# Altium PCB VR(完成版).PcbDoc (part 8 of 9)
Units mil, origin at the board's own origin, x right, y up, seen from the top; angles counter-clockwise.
Board outline 2839.68 x 2020.7 mil, 6 copper layers (TOP, GND02, SIN03, SIN04, PWR05, BOTTOM); 494 components, 404 nets, 7124 pads, 1123 vias.
Unrouted connection lines stored in the file: 10.
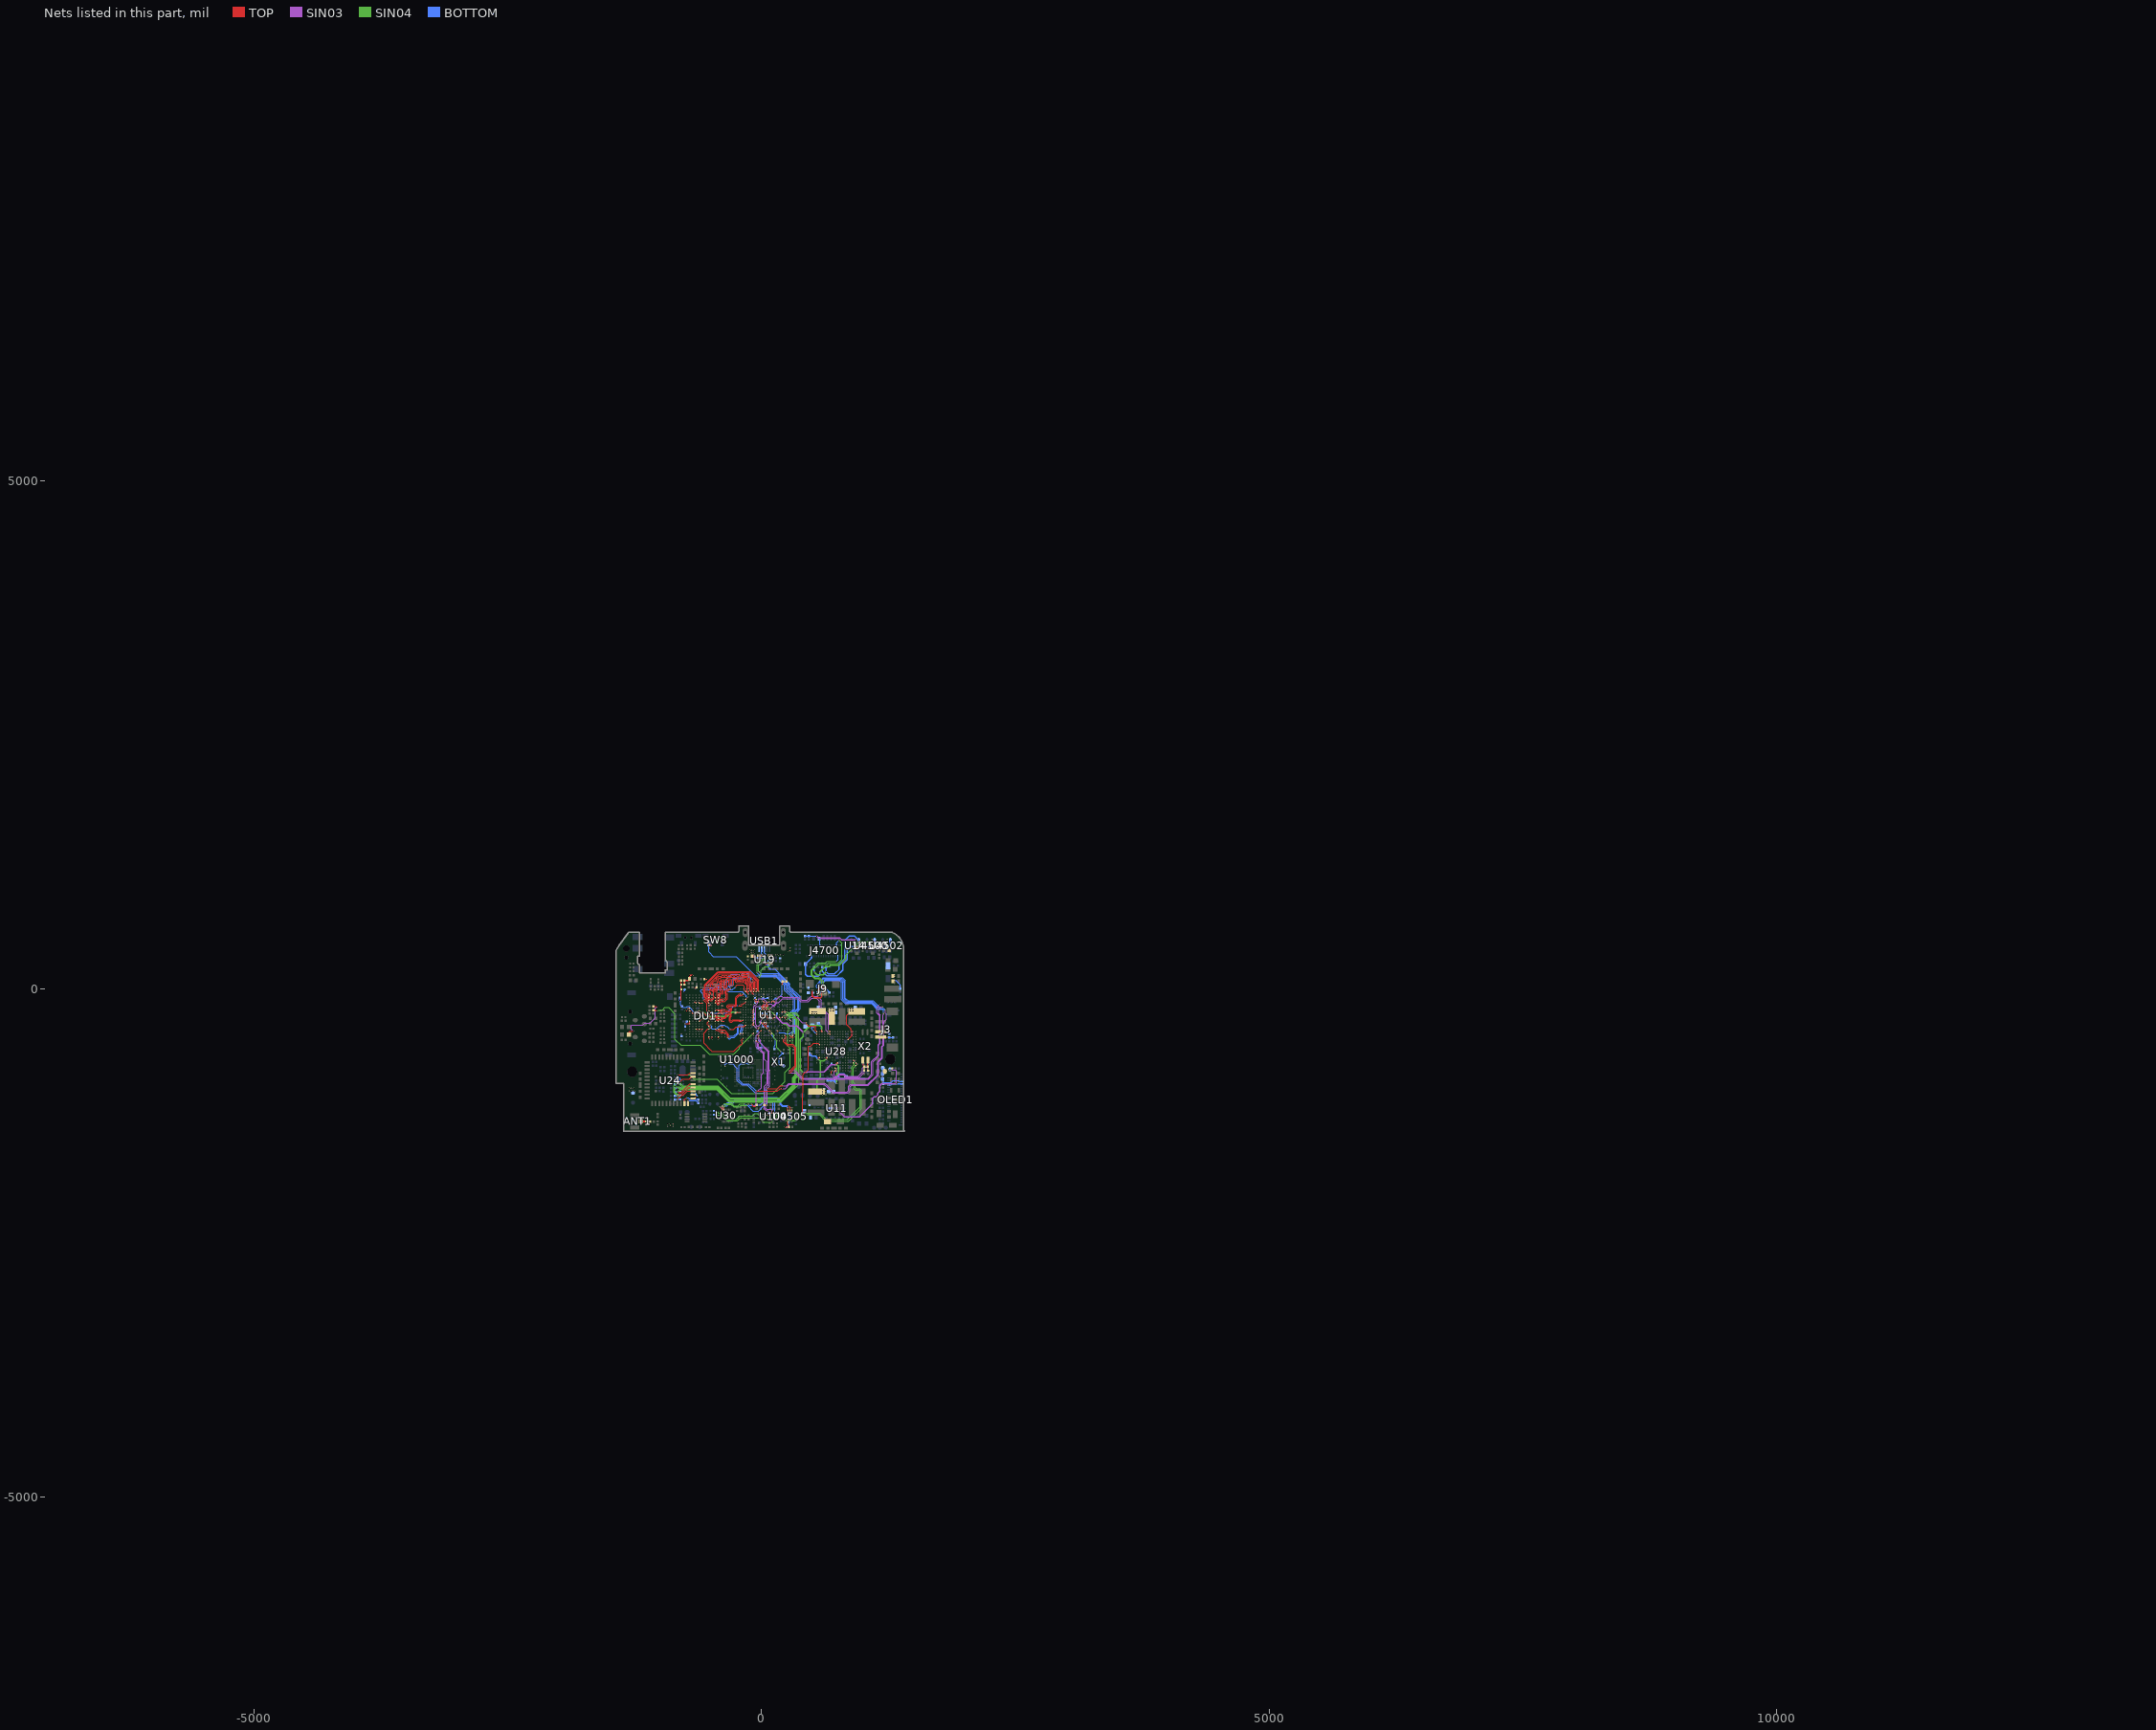
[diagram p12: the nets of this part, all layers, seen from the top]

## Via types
v1: diameter 14, hole 8, TOP to BOTTOM, tented both sides, 707 vias
v2: diameter 16, hole 10, TOP to BOTTOM, tented both sides, 275 vias
v3: diameter 16, hole 8, TOP to BOTTOM, tented both sides, 134 vias
v4: diameter 8, hole 8, TOP to BOTTOM, tented both sides, 3 vias
v5: diameter 10, hole 10, TOP to BOTTOM, tented both sides, 2 vias
v6: diameter 14, hole 8, TOP to BOTTOM, tented top, 1 vias
v7: diameter 14, hole 10, TOP to BOTTOM, tented both sides, 1 vias

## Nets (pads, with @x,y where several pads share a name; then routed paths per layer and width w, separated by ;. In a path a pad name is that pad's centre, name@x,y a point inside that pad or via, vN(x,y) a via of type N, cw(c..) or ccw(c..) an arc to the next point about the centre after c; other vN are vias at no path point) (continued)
SDQ24: DU1.B11 U1.A4 | length 880.9
  TOP w3.8: -415.58,-73.58 -411.3,-69.3 -411.3,-49.3
  TOP w4: DU1.B11@-423.02,-87.89 -415.58,-80.45 -415.58,-73.58 ; -411.3,-49.3 -401.81,-39.81 -393.01,-39.81 -389.01,-35.81 -389.01,-27.81 -393.01,-23.81 -404.01,-23.81 -406.01,-21.81 -406.01,-10.05 -410.01,-6.05 -415.01,-6.05 -419.01,-2.05 -419.01,5.95 -415.01,9.95 -410.01,9.95 -406.01,13.95 -406.01,21.95 -410.01,25.95 -415.01,25.95 -419.01,29.95 -419.01,37.95 -415.01,41.95 -410.01,41.95 -406.01,45.95 -406.01,53.95 -410.01,57.95 -415.01,57.95 -419.01,61.95 -419.01,69.95 -415.01,73.95 -410.01,73.95 -390.98,92.98 -369.01,92.98 -364.01,87.98 -364.01,21.98 -360.01,17.98 -355.01,17.98 -351.01,21.98 -351.01,92.95 -342.98,100.98 -309.01,100.98 -304.01,95.98 -304.01,52.98 -299.01,47.98 -293.01,47.98 -289.01,51.98 -289.01,87.98 -276.01,100.98 -254.54,100.98 -239.01,85.44 -239.01,77.98 -236.47,75.44 -194.52,75.44 -191.01,78.96 -191.01,87.95 -177.98,100.98 -162.01,100.98 -149.01,87.98 -149.01,59.9 -127.01,37.91 -127.01,23 -127.11,22.91 -127.11,4.61 U1.A4@-127.11,0
SDQ25: DU1.C10 U1.B4 | length 877
  TOP w4: DU1.C10@-454.52,-113.48 -440.46,-113.48 -436.42,-109.44 -436.42,-82.9 -430.67,-77.16 -430.67,-72.65 -439.08,-64.24 -439.08,-36.53 -453.58,-22.02 -469.02,-22.02 -474.01,-17.04 -474.01,-12.02 -470.01,-8.02 -449.01,-8.02 -440.01,-17.02 -434.01,-17.02 -431.01,-14.02 -431.01,29.98 -434.01,32.98 -479.01,32.98 -484.01,37.98 -484.01,43.63 -474.66,52.98 -434.01,52.98 -431.01,55.98 -431.01,74.92 -420.45,85.48 -420.45,91.13 -425.32,96.01 -425.32,101.66 -419.66,107.32 -414.01,107.32 -409.13,102.45 -403.48,102.45 -392.95,112.98 -249.01,112.98 -223.48,87.45 -209.53,87.45 -184.01,112.98 -149.01,112.98 -136.04,100.01 -136.04,85.81 ; -136.05,65.93 -136.05,85.81 ; -136.04,65.93 -136.04,65.61 -114.01,43.57 -114.01,-12.49 U1.B4@-127.11,-25.59
SDQ26: DU1.C11 U1.C4 | length 891.2
  TOP w3.8: -403.4,-74.4 -403.4,-66
  TOP w4: DU1.C11@-423.02,-113.48 -415.13,-105.59 ; -415.13,-103.7 -406.67,-95.25 -406.67,-77.67 -403.4,-74.4 ; -403.4,-66 -403.4,-55.4 -398.03,-50.03 -378.51,-50.03 -374.01,-45.53 -374.01,-11.81 -378.01,-7.81 -390.01,-7.81 -394.01,-3.81 -394.01,72.98 -389.01,77.98 -383.01,77.98 -379.01,73.98 -379.01,12.98 -370.52,4.49 -350.52,4.49 -339.01,16 -339.01,83.98 -335.01,87.98 -323.01,87.98 -319.01,83.98 -319.01,37.98 -314.01,32.98 -284.01,32.98 -274.01,42.98 -274.01,82.98 -269.01,87.98 -259.01,87.98 -254.01,82.98 -254.01,66.98 -250.01,62.98 -183.01,62.98 -179.01,66.98 -179.01,82.98 -174.01,87.98 -169.01,87.98 -164.01,82.98 -164.01,56.92 -140.42,33.33 -140.42,-37.87 U1.C4@-127.11,-51.19
SDQ27: DU1.B10 U1.B5 | length 863.6
  TOP w4: DU1.B10@-454.52,-87.89 -469.01,-73.4 -469.01,-37.1 -487.01,-19.1 -487.01,-8.05 -474.98,3.98 -447.01,3.98 -443.83,7.15 -443.83,13.98 -447.83,17.98 -494.01,17.98 -499.01,22.98 -499.01,45.6 -461.93,82.68 -456.28,82.68 -453.12,79.52 -447.46,79.52 -441.81,85.18 -441.81,90.83 -444.96,93.99 -444.96,99.65 -419.63,124.98 -391.65,124.98 -383.65,132.98 -375.65,132.98 -367.65,124.98 -359.65,124.98 -351.65,132.98 -343.65,132.98 -335.65,124.98 -327.65,124.98 -319.65,132.98 -311.65,132.98 -303.65,124.98 -295.65,124.98 -287.65,132.98 -279.65,132.98 -271.65,124.98 -263.65,124.98 -255.65,132.98 -247.65,132.98 -239.65,124.98 -230.65,124.98 -224.01,118.33 -224.01,107.98 -219.46,103.43 -210.55,103.43 -200.51,113.47 ; -200.48,113.47 -188.98,124.98 -141.01,124.98 -124.04,108.01 -124.04,80.84 ; -124.05,80.84 -124.05,70.9 -101.01,47.86 -101.01,23 -99.01,21 -99.01,-10.18 -101.52,-12.69 U1.B5@-101.52,-25.59
SDQ28: DU1.B9 U1.C6 | length 885.1
  TOP w4: DU1.B9@-486.01,-87.89 -485.15,-87.02 -474.01,-87.02 -469.01,-92.02 -469.01,-97.48 -473.01,-101.48 -495.56,-101.48 -505.51,-91.54 -505.51,-55.95 -499.01,-49.45 -499.01,-37.02 -511.01,-25.02 -511.01,-18.03 -507.01,-14.03 -503.01,-14.03 -499.01,-10.03 -499.01,-2.03 -503.01,1.97 -510.58,1.97 -513.08,4.47 -513.08,48.9 -414.01,147.98 -235.51,147.98 -213.01,125.48 -205.45,125.48 -193.95,136.98 -133.01,136.98 -112.04,116.01 -112.04,75.87 -89.01,52.83 -89.01,-47.02 -84.84,-51.18 U1.C6@-75.93,-51.18
SDQ29: DU1.B8 U1.A7 | length 839.6
  TOP w4: v3(-529.01,32.98) -530.42,31.56 -530.42,-67.9 -517.51,-80.82 DU1.B8@-517.51,-87.89 ; v3(-209.01,142.98) -205.62,142.98 -199.62,148.98 -123.95,148.98 -50.34,75.37 U1.A7@-50.34,0
  BOTTOM w4: v3(-529.01,32.98) -519.01,42.98 -394.01,42.98 -385.83,51.16 -380.17,51.16 -368.33,39.31 -362.67,39.31 -357.01,44.97 -357.01,50.63 -368.85,62.47 -368.85,68.13 -363.2,73.78 -357.54,73.78 -345.7,61.94 -340.04,61.94 -334.38,67.6 -334.38,73.25 -346.23,85.1 -346.23,90.75 -294.01,142.98 v3(-209.01,142.98)
SDQ30: DU1.C8 U1.B8 | length 910.7
  TOP w4: DU1.C8@-517.51,-113.48 -525.86,-113.48 -541.51,-97.84 -541.51,-89.82 -553.5,-77.83 -553.5,-51.12 -559.08,-45.54 -559.08,38.96 -432.1,165.95 -425.07,172.98 -120.01,172.98 -114.01,172.98 -26.32,85.29 -26.32,-24.02 U1.B8@-24.75,-25.59
SDQ31: DU1.C9 U1.B7 | length 897.5
  TOP w4: DU1.C9@-486.01,-113.48 -500.54,-113.48 -512.54,-101.48 -522.84,-101.48 -530.42,-93.9 -530.42,-83.87 -541.5,-72.79 -541.5,-46.15 -548.08,-39.56 -548.08,35.47 -422.58,160.98 -118.98,160.98 -35.58,77.58 -35.58,-10.84 U1.B7@-50.34,-25.59
SDQM0: DU1.L8 U1.R3 | length 496.8
  TOP w4: DU1.L8@-517.51,-318.2 -530.42,-331.12 -530.42,-349.9 -523.3,-357.02 v1(-504.01,-357.02) ; v1(-310.26,-400.3) -271.28,-400.3 -246.42,-375.44 -229.03,-375.44 -225.55,-371.96 -166.38,-371.96 U1.R3@-152.7,-358.27
  BOTTOM w4: v1(-504.01,-357.02) -490.08,-370.95 -490.08,-387.53 -484.08,-393.53 -440.51,-393.53 -401.51,-354.53 -366.08,-354.53 -349.08,-371.53 -336,-371.53 -312.08,-395.45 -312.08,-396.8 -310.26,-398.62 v1(-310.26,-400.3)
SDQM1: DU1.P8 U1.Y2 | length 662.6
  TOP w4: DU1.P8@-517.51,-394.98 -526.03,-394.98 -565.5,-434.45 -565.5,-534.47 -500.68,-599.29 -493.65,-606.32 -486.63,-613.35 -334.22,-613.35 -324.28,-613.35 -314.34,-613.36 -274.57,-613.36 -273.91,-613.35 -207.48,-546.92 -197.83,-546.92 -189.11,-538.2 -189.11,-525.85 -191.03,-523.93 -191.03,-498.96 U1.Y2@-178.29,-486.23
SDQM2: DU1.G8 U1.F3 | length 429.9
  TOP w4: DU1.G8@-517.51,-215.84 v1(-504.71,-228.64) ; v1(-226.04,-162.99) -222.51,-166.53 -197.08,-166.53 -191.97,-161.42 -191.97,-149.46 -184.16,-141.64 -166.38,-141.64 U1.F3@-152.7,-127.96
  BOTTOM w4: v1(-504.71,-228.64) -492.39,-228.64 -482.5,-238.53 -341.51,-238.53 -265.97,-162.99 v1(-226.04,-162.99)
SDQM3: DU1.D8 U1.B3 | length 766.4
  TOP w4: v3(-574.01,12.98) -574.01,-5.81 -569.01,-10.81 -569.01,-52.58 -565.5,-56.09 -565.5,-79.82 -550.08,-95.24 -550.08,-106.5 DU1.D8@-517.51,-139.07 ; v1(-259.01,17.98) -239.01,37.98 -184.01,37.98 -166.38,20.35 -166.38,-11.91 -161.83,-16.47 U1.B3@-152.7,-25.59
  BOTTOM w4: v3(-574.01,12.98) -467.26,12.98 -452.26,27.98 -444.26,27.98 -440.26,23.98 -440.26,8.48 -436.26,4.48 -428.26,4.48 -424.26,8.48 -424.26,23.98 -420.26,27.98 -412.26,27.98 -408.26,23.98 -408.26,8.48 -404.26,4.48 -396.26,4.48 -392.26,8.48 -392.26,23.98 -388.26,27.98 -380.26,27.98 -376.26,23.98 -376.26,8.48 -372.26,4.48 -341.93,4.48 -340.61,3.15 -329.54,-7.91 -284.89,-7.91 v1(-259.01,17.98)
SDQS0: DU1.L10 U1.N1 | length 395.5
  TOP w3.8: DU1.L10@-454.52,-318.2 -442.76,-306.45 -442.76,-302.85 -437.82,-297.91 -437.82,-285.27 -435.83,-283.28 ; -354.01,-271.35 -354.01,-252.02 -341.51,-239.52 -303.83,-239.52 -294.01,-249.35 -294.01,-269.7 -304.01,-279.7 -304.01,-311.52 -301.01,-314.52 -294.01,-314.52 -281.51,-302.02 -219.07,-302.02 -214.01,-307.09 -204.94,-307.09 U1.N1@-203.88,-307.09
  TOP w4: -435.83,-283.28 -433.08,-280.53 -417.08,-280.53 -413.58,-277.03 -402.58,-277.03 -399.58,-280.03 -362.69,-280.03 -354.01,-271.35
SDQS0B: DU1.L11 U1.N2 | length 395.8
  TOP w3.8: DU1.L11@-423.02,-318.2 -425.31,-318.2 -430.26,-313.26 -430.26,-309.71 -427.08,-306.53 -401.08,-306.53 -399.08,-304.53 -386.67,-304.53 -374.32,-292.17 -357.16,-292.17 -341.5,-276.52 -341.5,-267.39 -341.51,-257.2 -336.33,-252.02 -309.01,-252.02 -306.51,-254.52 -306.51,-264.52 -316.51,-274.53 -316.51,-319.52 -309.01,-327.02 -299.18,-327.02 -288.83,-327.03 -276.33,-314.52 -224.25,-314.52 -219.18,-319.59 -199.76,-319.59 -198.7,-319.59 -191.38,-312.27 -186.13,-307.02 -182.97,-307.02 -182.91,-307.09 U1.N2@-178.29,-307.09
SDQS1: DU1.P10 U1.V1 | length 508.2
  TOP w3.8: DU1.P10@-454.52,-394.98 -442.01,-407.48 -418.55,-407.48 -406.42,-419.61 -406.42,-424.9 -397.8,-433.53 -355.18,-433.53 -334.57,-454.13 -334.57,-476.59 v1(-335.01,-477.02)
  TOP w4: v1(-217.52,-447.84) U1.V1@-204.73,-435.04
  BOTTOM w3.8: -318.46,-491.53 -308.08,-491.53 -293.58,-477.02 -266.33,-477.02 -223.94,-434.64 -223.94,-379.64 -208.83,-364.52 -199.18,-364.52 -196.51,-367.2 -196.51,-396.85 -206.51,-406.85 -206.51,-438.52 v1@-216.11,-448.12
  BOTTOM w4: v1(-335.01,-477.02) -320.5,-491.53 -318.46,-491.53
SDQS1B: DU1.P11 U1.V2 | length 483.6
  TOP w3.8: DU1.P11@-423.02,-394.98 -409.35,-394.98 -397,-407.33 -385.58,-407.33 ; -363.7,-407.33 -346.95,-424.08 -321.5,-449.53 -321.5,-468.11 v1@-315.58,-474.03
  TOP w4: -385.58,-407.33 -381.28,-403.03 -368,-403.03 -363.7,-407.33 ; v1(-191.93,-447.84) U1.V2@-179.14,-435.04
  BOTTOM w3.8: v1@-317.97,-474.34 -317.97,-468.96 -313.53,-464.52 -291.15,-464.52 -271.51,-464.52 -236.44,-429.46 -236.44,-374.46 -214.01,-352.02 -194.01,-352.02 -184.01,-362.02 -184.01,-402.02 -194.01,-412.02 v1@-194.01,-444.61
  other v1: -314.01,-477.02
SDQS2: DU1.G10 U1.C1 | length 457.8
  TOP w3.8: DU1.G10@-454.52,-215.84 -442.02,-203.34 -385.4,-203.34 -382.58,-200.53 -367.97,-200.53 -358.97,-209.52 -304.43,-209.52 -301.51,-206.6 -301.51,-197.75 -304.38,-194.87 -320.73,-194.87 -335.58,-180.03 -335.58,-163.6 -325.41,-153.42 -272.61,-153.42 -264.43,-161.6 -259.01,-161.6 -254.77,-157.37 -254.77,-102.3 -254.78,-86.12 -247.46,-78.79 -234.01,-65.35 -227.17,-58.51 -219.85,-51.18 -207.83,-51.18 U1.C1@-203.88,-51.19
SDQS2B: DU1.G11 U1.C2 | length 457.3
  TOP w3.8: DU1.G11@-423.02,-215.84 -409.48,-215.84 -396.8,-228.53 -382.08,-228.53 -380.58,-230.03 -366.98,-230.03 -358.97,-222.02 -299.25,-222.02 -289.01,-211.78 -289.01,-192.57 -299.2,-182.37 -316.51,-182.37 -323.83,-175.05 -323.83,-169.53 -320.23,-165.92 -277.78,-165.92 -269.61,-174.1 -253.83,-174.1 -242.27,-162.55 -242.27,-91.29 -214.67,-63.68 -190.79,-63.68 U1.C2@-178.29,-51.18
SDQS3: DU1.D10 U1.B6 | length 810.6
  TOP w3.8: DU1.D10@-454.52,-139.07 -440.78,-125.33 -418.12,-125.33 -405.32,-112.54 -405.32,-106.77 -400.08,-101.53 -386.08,-101.53 -380.58,-96.03 -369.58,-96.03 -365.08,-100.53 -355.08,-100.53 -346.51,-91.95 -346.51,-57.38 -357.97,-45.91 -357.97,-18.91 -347.97,-8.91 -333.57,-8.91 -320.01,4.65 v1(-320.01,7.98) ; v1(-94.01,97.98) -63.43,67.4 -63.43,-13.09 U1.B6@-75.93,-25.59
  BOTTOM w3.8: v1(-320.01,7.98) -320.01,8.98 -324.01,12.98 -324.01,27.98 -309,42.98 -289,42.98 -284.01,47.98 -284.01,94.52 -266.71,111.81 -192.84,111.81 -187.16,117.5 -187.16,147.15 -187.16,157.5 -179.84,164.83 -179.01,165.65 -171.69,172.98 -161.33,172.98 -148.18,172.98 -119.01,143.8 -119.01,122.98 v1(-94.01,97.98)
SDQS3B: DU1.D11 U1.A6 | length 798.2
  TOP w3.8: DU1.D11@-423.02,-139.07 -424.26,-137.83 -435.6,-137.83 -439.01,-141.24 -439.01,-148.32 -435.31,-152.02 -419.01,-152.02 -408.29,-141.31 -408.29,-134.23 -401.08,-127.03 -383.58,-127.03 -381.08,-124.53 -362.22,-124.53 ; -333.91,-96.21 -333.91,-51.97 -345.47,-40.4 -345.47,-24.09 -342.8,-21.41 -328.39,-21.41 v1(-299.01,7.98) ; v1(-89.01,72.98) -75.93,59.9 U1.A6@-75.93,0
  TOP w4: -362.22,-124.53 -333.91,-96.21
  BOTTOM w3.8: v1(-299.01,7.98) -309.51,18.48 -309.51,24.8 -303.83,30.48 -283.83,30.48 -280.17,34.14 -271.5,42.8 -271.5,53.16 -271.51,89.34 -261.53,99.31 -187.67,99.31 -174.66,112.33 -174.66,152.33 -166.51,160.48 -153.36,160.48 -131.51,138.62 -131.51,117.8 -107.71,94 -107.71,66.68 -104.01,62.98 -94.01,62.98 -89.01,67.98 v1(-89.01,72.98)
SENSOR_VCC: J4700.30
SODT0: DU1.J8 U1.E3 | length 804.6
  TOP w4: v1@-567.01,-100.31 -565.51,-101.81 -565.51,-107.78 ; -565.5,-107.78 -565.5,-114.11 -534.08,-145.53 -534.08,-250.45 DU1.J8@-517.51,-267.02 ; U1.E3@-153.54,-102.37 v1(-140.74,-89.57)
  BOTTOM w4: v1@-567.01,-100.31 -567.01,-60.23 -599.01,-28.23 -599.01,-15.81 -592.04,-8.85 -395.29,-8.85 -345.59,-8.84 -327.4,-27.02 -192.01,-27.02 -150.51,-68.52 -150.51,-78.96 v1@-139.9,-89.57
  other v1: -565.01,-100.31
SPOLN: C330.1 U28.E2 | length 2200.6
  TOP w8: U28.E2@904.95,-702.6 v3(917.75,-715.4)
  SIN04 w8: v2@-441.5,-1202.08 v2@-440.29,-1203.29 ; v2(-441,-1204) -420.56,-1224.44 -387.22,-1224.44 -326.66,-1285 -243,-1285 -211,-1253 -86,-1253 -63,-1230 -39,-1230 11,-1280 112,-1280 160,-1232 194,-1232 250,-1288 332,-1288 397,-1223 575,-1223 638,-1286 850,-1286 972,-1164 972,-1006 962,-996 923,-996 909,-982 909,-949 890,-930 890,-769.49 917.75,-741.75 v3(917.75,-715.4)
  BOTTOM w8: C330.1@-468.75,-1202.08 v2@-441.5,-1202.08
SPOLP: C328.1 U28.D1 | length 2179.2
  TOP w8: U28.D1@930.54,-728.19 v3(943.34,-740.98)
  SIN04 w8: v2@-442.5,-1241.08 -393.92,-1241.08 -338,-1297 -233,-1297 -208,-1272 -21,-1272 21,-1314 99.21,-1314 166.21,-1247 187.79,-1247 240.79,-1300 341.21,-1300 403.21,-1238 570,-1238 633,-1301 856.69,-1301 984,-1173.69 984,-999 968,-983 932,-983 923,-974 923,-942 904,-923 904,-780.32 v3(943.34,-740.98)
  BOTTOM w8: C328.1@-468.75,-1241.08 v2@-442.5,-1241.08
  other v2: -442.5,-1244.08
SPORN: U28.D2
SPORP: U28.C1
SVREF: DC7.2 DC8.1 DC9.2 DC20.2 DC21.2 DR1.1 DR7.2 DU1.H4 DU1.J11 U1.K1 | length 1197.9
  TOP w4: v1(-599.2,-228.64) -598.31,-229.53 -575.57,-229.53 -575.11,-229.53 -525.61,-279.03 -447.2,-279.03 -435.2,-267.02 DU1.J11@-423.02,-267.02
  TOP w10: v1(-801.97,-113.91) -789.01,-100.94 DC9.2@-789.01,-4.86 DR1.1@-789.01,83.14 ; v1@-656.29,-228.64 -643.92,-241.01 DU1.H4@-643.49,-241.43 ; DC7.2@-254.01,-237.02 -244.03,-227.05 v1(-222.5,-227.05) -207.15,-227.05 U1.K1@-203.88,-230.32
  SIN04 w14: v1(-599.2,-228.64) -570.39,-228.64 -525.51,-273.53 -339.59,-273.53 -293.11,-227.05 v1(-222.5,-227.05)
  BOTTOM w5: DC21.2@-802.27,-85.86 -802.27,-113.61 v1(-801.97,-113.91)
  BOTTOM w10: v1(-801.97,-113.91) -794.01,-121.88 -794.01,-158.32 DC20.2@-780.42,-171.9 -771.3,-181.03 -737.58,-181.03 -731.08,-174.53 -717.08,-174.53 -662.97,-228.64 v1(-599.2,-228.64)
  other v1: -657.42,-228.9
TC-STBY: U1.C10
TOUCH_INT: ED28.1 J9.1 U1.Y18 | length 3030.6
  TOP w5: U1.Y18@230.31,-486.23 217,-499.54 217,-522 254,-559 303,-559 332,-588 332,-756 284,-804 v1(269,-804) ; J9.1@557.04,-40.86 v1(557.04,0.83)
  SIN03 w4: v1(269,-804) 329,-804 404.3,-879.3 1051.7,-879.3 1087.3,-843.7 1087.3,-713.7 1149.02,-651.98 1149.02,-546.98 1163.1,-532.9 1163.1,-266.1 1137,-240 1137,-188 v1(1165,-160)
  BOTTOM w5: ED28.1@550.53,-35.86 557.04,-29.34 v1(557.04,0.83) 542,15.87 542,37 571,66 571,74 609,112 796,112 828,80 828,-89.85 853.15,-115 1097,-115 1142,-160 v1(1165,-160)
TOUCH_RST: ED29.1 J9.2 U1.W18 | length 3131.3
  TOP w5: U1.W18@230.31,-460.63 243.11,-473.42 243.11,-532.11 256,-545 308,-545 342,-579 342,-766 282,-826 v1(269,-826) ; v1(557.73,27.14) 576.73,8.14 J9.2@576.73,-40.86
  SIN03 w4: v1(269,-826) 335,-826 398.2,-889.2 1055.8,-889.2 1097.2,-847.8 1097.2,-717.8 1157,-658 1157,-552 1172,-537 1172,-257 1156,-241 1156,-197 1178,-175 v1(1192,-175)
  BOTTOM w5: ED29.1@586.73,-32.46 ED29.1@590.13,-35.86 573.73,-19.46 573.73,11.14 v1(557.73,27.14) 583,52.41 583,69.03 615.97,102 789.03,102 816,75.03 816,-94.82 846.18,-125 1091,-125 1141,-175 v1(1192,-175)
TWI0-SCK: ED32.1 J9.4 J4700.27 R497.1 R518.1 U1.U9 U1000.3 | length 5058.8
  TOP w4: v1(-12.8,-422.24) U1.U9@0,-409.45
  TOP w5: v1(-99.27,-1135.86) -77.13,-1158 -58.79,-1158 R518.1@-45.27,-1144.48 ; v1(-51,-1008) 158,-1008 183,-983 v1(205,-983) ; v1(597.1,27.14) 616.1,8.14 J9.4@616.1,-40.86
  SIN03 w4: v1(-99.27,-1135.86) -86.13,-1149 -65,-1149 -50,-1134 -50,-1008 -35,-1008 -1,-974 -1,-848 18,-829 18,-641 -52,-571 -52,-461.45 v1(-12.8,-422.24) ; v1(205,-983) 235,-983 276,-942 618,-942 702,-1026 855,-1026 872,-1009 872,-962 885,-949 1052,-949 1155,-846 1155,-719 1192,-682 1192,-570 1208,-554 1208,-323 1231,-300 1231,-244 1223,-236 v1(1223,-211)
  SIN04 w4: v1(597.1,27.14) 597.1,65.9 563,100 525,100 490,135 490,187 559,256 633,256 646,269 v1(735,269)
  BOTTOM w5: R497.1@-124,-731 -125.4,-732.4 -194.4,-732.4 -219,-757 -219,-896 -181,-934 -125,-934 v1(-51,-1008) ; ED32.1@629.73,-35.86 597.1,-3.23 v1(597.1,27.14) 597.1,63.19 625.91,92 779.09,92 801.9,69.19 801.9,-100.66 836.25,-135 1088,-135 1142,-189 1201,-189 v1(1223,-211) ; v1(735,269) 753.54,287.54 J4700.27@753.54,322.48
TWI0-SDA: ED33.1 J9.5 J4700.26 R498.1 R517.1 U1.W8 U1000.4 | length 5156.1
  TOP w4: v1(-38.39,-473.42) U1.W8@-25.59,-460.63
  TOP w5: R517.1@29.73,-1144.48 v2(56.35,-1144.48) ; v1(57,-985) 156,-985 185,-956 v1(215,-956) ; J9.5@635.78,-40.86 v1(635.78,0.83)
  SIN03 w4: v1(-38.39,-473.42) -6,-505.81 -6,-533 77,-616 77,-798 81,-802 81,-960.35 56.35,-985 v2(56.35,-1144.48) ; v1(215,-956) 246,-956 271,-931 628,-931 713,-1016 846,-1016 860,-1002 860,-959 878,-941 1048,-941 1144.99,-844.01 1144.99,-714.01 1183,-676 1183,-567 1197,-553 1197,-259 1202,-254 v1(1202,-242)
  SIN04 w4: v1(635.78,0.83) 613,23.61 613,68 570,111 531,111 503,139 503,180 566,243 653,243 662.84,252.84 755.84,252.84 792,289 792,449.87 v1(764.73,477.14)
  BOTTOM w5: v1(-356,-760) R498.1@-356,-733 -301.83,-733 -294.42,-725.58 -237,-783 -237,-901 -192,-946 -140,-946 -62,-1024 18,-1024 v1(57,-985) ; ED33.1@669.33,-35.86 669.33,-32.72 v1(635.78,0.83) 619,17.61 619,30 610,39 610,57.85 634.15,82 770.85,82 789,63.85 789,-106 827,-144 1083,-144 1138,-199 1192,-199 1202,-209 v1(1202,-242) ; J4700.26@741.73,431.14 741.73,454.14 v1(764.73,477.14)
TWI1-SCK: R6.1 R519.1 U1.Y8 U30.23 U100.12 U4505.13 | length 2486
  TOP w4: v1(-38.39,-499.02) U1.Y8@-25.59,-486.23
  TOP w5: v2(-383.27,-1154.86) -368.89,-1169.24 U30.23@-368.89,-1189.8 ; U100.12@110.89,-1223.15 v2(110.89,-1204.02) ; v2(261.73,-1146.86) 281.73,-1166.86 U4505.13@281.73,-1203.66
  SIN03 w4: v1(-38.39,-499.02) -20,-517.41 -20,-537 -27.84,-544.84 -27.84,-566.16 -15,-579 23,-579 65,-621 65,-806 69,-810 69,-944 42,-971 42,-1176 53,-1187 93.87,-1187 v2(110.89,-1204.02)
  SIN04 w4: v2(-383.27,-1154.86) -359.41,-1131 -291,-1131 -270,-1152 -229,-1152 -212.86,-1135.86 v1(-163,-1135.86)
  BOTTOM w5: v2(-383.27,-1154.86) -366.27,-1137.85 -348.85,-1137.85 -332,-1121 -293,-1121 -267,-1095 -26,-1095 3,-1066 151,-1066 195,-1110 195,-1134 207.86,-1146.86 v2(261.73,-1146.86) ; v1(-163,-1135.86) -149.42,-1149.44 -136.56,-1149.44 -83,-1203 -28.79,-1203 R519.1@29.73,-1144.48 57.35,-1116.86 105.73,-1116.86 115.73,-1126.86 v2@115.73,-1199.17 ; v1(-38.39,-499.02) 6,-543.41 6,-575.98 R6.1@-2.5,-584.48
TWI1-SDA: R7.1 R520.1 U1.AA7 U30.24 U100.2 U4505.14 | length 2532.9
  TOP w4: U1.AA7@-51.18,-511.82 v1(-38.38,-524.61)
  TOP w5: v2@-409.27,-1157.86 -384.64,-1182.49 U30.24@-384.64,-1189.8 ; v2(63.57,-1244.02) U100.2@90.02,-1244.02 ; U4505.14@262.04,-1203.66 v2(262.04,-1172.54)
  SIN03 w4: v1(-38.38,-524.61) -38.38,-568.62 28,-635 28,-693 51,-716 51,-813 59,-821 59,-933 31,-961 31,-1182 47,-1198 63,-1198 75,-1210 75,-1232.59 v2(63.57,-1244.02)
  SIN04 w4: v2(-407.27,-1155.86) -394.13,-1169 -375,-1169 -345,-1139 -298,-1139 -273,-1164 -217,-1164 -203,-1150 -145.14,-1150 v1(-131,-1135.86)
  BOTTOM w5: v2@-409.27,-1157.86 -396.13,-1171 -379,-1171 -358.22,-1150.22 -340.22,-1150.22 -323,-1133 -285,-1133 -259.14,-1107.14 -20.97,-1107.14 8.17,-1078 145.83,-1078 182.86,-1115.03 182.86,-1139.03 202.83,-1159 248.5,-1159 v2(262.04,-1172.54) ; v1(-131,-1135.86) -116.86,-1150 -50.79,-1150 R520.1@-45.27,-1144.48 -8.48,-1144.48 31.14,-1104.86 113.73,-1104.86 131.73,-1122.86 131.73,-1215.86 127.59,-1220 87.59,-1220 v2(63.57,-1244.02) ; R7.1@-37.75,-584.48 v1@-37.75,-525.25
UART0-RX: U1.D9
UART0-TX: U1.A9
UBOOT: D38.1 SW8.1 U1.U15 | length 1720.5
  TOP w4: U1.U15@153.54,-409.45 v1(166.33,-422.25)
  TOP w5: D38.1@-515.27,432.14 -488.27,432.14 v1(-487.27,433.14)
  BOTTOM w5: v1(-487.27,433.14) -504.55,433.14 SW8.1@-517.78,446.37 -517.78,363.78 -474,320 -250,320 -61,131 147,131 240,38 240,-2 331,-93 331,-199 311,-219 311,-413 281,-443 238,-443 225.96,-430.96 175.04,-430.96 v1(166.33,-422.25)
USB1-DRVVBUS: U1.Y17
USB-5V: C93.2 C94.2 C182.2 OD1.2 R22.1 U19.5 | length 109.2
  BOTTOM w5: v1(1315.73,91.64) 1365.73,41.64 R22.1@1365.73,3.14
  other v1: 1315.73,49.14 1315.73,70.39 1315.73,112.89 1315.73,134.14 143.73,338.14 167.73,338.14 191.73,338.14 217.73,338.14
USB-DM0: D31.1 U1.W20 USB1.2 | length 1292.2
  TOP w5: U1.W20@281.5,-460.63 294.3,-473.42 v1(319.89,-473.42)
  SIN04 w5.5: v1(-46,163) -40.25,168.75 -40.25,238.01 27,305.26 27,326 v1(23,330)
  BOTTOM w5: v1(-46,163) -24,141 158,141 258,41 258,8.86 359,-92.14 359,-190 322,-227 322,-422 302.09,-441.91 302.09,-455.63 v1(319.89,-473.42) ; USB1.2@3.14,391.45 3.14,348 21.13,330 D31.1@3.73,312.59 ; D31.1@3.73,312.59 3.73,312.14 -0.82,307.59 D31.1@-1.27,307.59 D31.1@3.73,312.59
USB-DM1: U1.AA20
USB-DP0: D30.1 U1.W21 USB1.3 | length 1213.4
  TOP w4: U1.W21@307.09,-460.63 v1(319.89,-447.83)
  SIN04 w5.5: v1(-23,165) -28.75,170.75 -28.75,233.25 38.5,300.5 38.5,324.77 v1(43.73,330)
  BOTTOM w5: v1(-23,165) -9,151 162.14,151 268,45.14 268,13 369,-88 369,-194.14 332,-231.14 332,-435.72 v1(319.89,-447.83) ; D30.1@28.73,313.59 D30.1@34.73,307.59 44,316.87 v1@44,329.73 ; USB1.3@28.73,391.45 28.73,354.27 43.73,339.27 v1(43.73,330)
USB-DP1: U1.Y20
USB-DRVVBUS: R139.2 U19.4 U28.T16 | length 1067.1
  TOP w5: v1@38.73,237.14 52.33,250.74 U19.4@90.91,250.74 ; v1(445,-333) 445,-346 465,-366 528,-366 536,-374 536,-410.42 U28.T16@546.68,-421.1
  SIN03 w4: v1@344,-273 404,-333 v1(445,-333)
  BOTTOM w5: v1@38.73,237.14 R139.2@70.73,237.14 70.73,209.27 84,196 133,196 281,48 281,22 383,-80 383,-197 344,-236 v1@344,-273
  other v1: 346,-273 38.73,233.14
USB-ID: R140.1 U1.N20 | length 972.5
  TOP w4: U1.N20@281.5,-307.09 v1(294.3,-319.89)
  SIN04 w4: v1(-23,117) -3,137 -3,183 34,220 73,220 82.96,229.96 v1@82.96,285
  BOTTOM w5: v1@-23,120 142,120 228,34 228,-11 315,-98 315,-200 278,-237 278,-303.59 v1(294.3,-319.89) 295.89,-319.89 v1@295.09,-319.09 ; R140.1@70.73,273.76 v1(82.96,286) v1@82.96,285
USBVBUS: C183.2 C184.2 C266.2 D36.1 R463.2 U19.1 U28.R16 USB1.1 | length 106.4
  TOP w5: 533.89,-433.89 U28.R16@546.68,-446.69
  BOTTOM w5: C266.2@502.41,-358.64 502.41,-402.42 533.89,-433.89
  other v1: -113.27,357.14 -90.77,357.14 -68.27,357.14 285,373.14 263.73,375 -113.27,377.14 -90.77,377.14 -68.27,377.14 286,401.14
  other v2: 514,-385
  other v3: 512,-408 488,-383
VBAT: C264.2 C267.2 R319.1 TP70.1 U28.L15 | length 843.6
  TOP w5: v2(417.73,-1254.86) 406,-1243.13 406,-1029 413,-1022 413,-843 461,-795 461,-569 468,-562 488.74,-562 514.5,-536.24 559.46,-536.24 U28.L15@572.27,-549.05
  other v1: -896.27,-1357 -872.27,-1356 -920.27,-1355 -872.27,-1332 -922,-1330.86 -898,-1330.86 -1298,-1006.86 -1276,-1006.86 -1254,-1006.86 -1300.27,-980 -1278.27,-980 -1256.27,-980
VCC15_DVP: C4510.2 R4706.1 U4502.5 | length 991.5
  BOTTOM w15: R4706.1@598.93,215.81 598.93,175.07 646,128 743,128 802,187 802,247 845,290 845,386 873,414 1248,414 1270.23,436.23 U4502.5@1270.23,477.14
  other v1: 1242.23,465.14 1242.23,485.14
VCC18_DVP: C205.1 C4703.1 J4700.12 R4700.1 R4701.1 R4704.2 R4705.1 U14.5 | length 1500.3
  SIN03 w15: v1(543.95,520.14) 565.1,499 776,499 793.86,481.14 v1(933.73,481.14)
  SIN04 w15: v1(520.13,166) 547.13,139 609.66,139 v1(638.33,167.67)
  BOTTOM w10: R4701.1@429.37,521.52 R4700.1@468.73,521.52 542.58,521.52 v1(543.95,520.14) C4703.1@569.73,494.37 576.37,487.72 J4700.12@576.37,431.14
  BOTTOM w15: v1(520.13,166) R4704.2@520.13,215.81 ; R4705.1@638.33,215.81 v1(638.33,167.67) 659,147 721,147 766,192 766,244 823,301 823,479 863,519 919.37,519 U14.5@961.23,477.14
  other v1: 933.73,461.14
VCC28_DVP: C4504.1 C4702.1 J4700.5 U4500.5 | length 1044.2
  SIN04 w15: v1(577,166) 630,219 667,219 680.6,232.6 767.6,232.6 829,294 829,330 964.14,465.14 v1(1087.73,465.14)
  BOTTOM w15: J4700.5@493.7,322.48 493.7,303.11 435.73,245.14 C4702.1@433.73,245.14 433.73,143.27 453,124 560,124 577,141 v1(577,166)
  other v1: 1087.73,485.14
VCC-DRAM: C65.2 C88.2 DC2.2 DC3.2 DC4.2 DC5.2 DC6.2 DC8.2 DC10.2 DC11.2 DC12.2 DC13.2 DC14.2 DC15.2 DC16.2 DC17.2 DR1.2 DU1.A8 DU1.A9 DU1.A11 DU1.C12 DU1.D4 DU1.D5 DU1.D6 DU1.E8 DU1.E12 DU1.F2 DU1.G2 DU1.G5 DU1.G12 DU1.H3 DU1.H5 DU1.H6 DU1.H8 DU1.H9 DU1.H11 DU1.H12 DU1.J5 DU1.J6 DU1.J9 DU1.J10 DU1.K5 DU1.K6 DU1.K8 DU1.K11 DU1.K12 DU1.L2 DU1.L5 DU1.L12 DU1.M2 DU1.N8 DU1.N12 DU1.P4 DU1.P5 DU1.P6 DU1.R12 DU1.U8 DU1.U9 DU1.U11 L6.2 U1.E7 U1.F7 U1.J6 U1.K6 U1.L6 U1.M6 U1.N6 U1.P6 U1.R6 U28.F12 U28.F15 | length 2349.3
  TOP w4: DU1.K5@-612,-292.61 -612,-294.03 -607,-294.03 -595.62,-305.41 v1@-593.3,-305.41 ; v1(-441.72,-254.23) DU1.H11@-428.93,-241.43 ; DU1.K11@-423.02,-292.61 DU1.K11@-422.61,-293.02 ; v1@-409.01,-293.02 -408.01,-292.02 -407.41,-292.61 v1(-407.01,-292.61) ; DU1.H12@-392.92,-240.04 DU1.H12@-391.53,-241.43 ; v1@-373.04,-215.84 v1(-372.97,-215.91)
  TOP w5: DU1.H11@-423.02,-241.43 -416.11,-234.53 -403.58,-234.53 -398.06,-240.04 DU1.H12@-392.92,-240.04
  TOP w8: v1(-424.01,-42.02) -423.02,-43.01 DU1.A11@-423.02,-62.3 ; DU1.K11@-422.61,-293.02 v1@-409.01,-293.02 ; v1(-407.01,-292.61) DU1.K12@-391.53,-292.61 ; DU1.L12@-391.53,-318.2 v1(-360.19,-318.2) ; DU1.G12@-391.53,-215.84 v1@-373.04,-215.84 ; DU1.E12@-391.53,-164.66 v1@-373.43,-164.66 ; DU1.C12@-391.53,-113.48 v1@-373.43,-113.48
  TOP w10: v1(-747.82,-343.8) DU1.M2@-706.49,-343.8 DU1.L2@-706.49,-318.2 ; v1(-746.91,-215.84) v1(-724.58,-215.84) -701.04,-215.84 v1(-688.25,-228.64) -687.79,-228.64 DU1.H3@-674.99,-241.43 ; v1@-728.02,-190.25 v1(-725.18,-193.09) -723.97,-193.09 -721.13,-190.25 DU1.F2@-706.49,-190.25 ; v1@-656.29,-126.28 DU1.D4@-643.49,-139.07 ; DU1.P4@-643.49,-394.98 -637.59,-394.98 -624.79,-407.77 DU1.P5@-612,-394.98 -606.09,-394.98 -593.3,-407.77 DU1.P6@-580.5,-394.98 ; v1@-627.42,-128.9 -622.16,-128.9 DU1.D5@-612,-139.07 DU1.D6@-580.5,-139.07 ; DU1.L5@-612,-318.2 -606.09,-318.2 -593.3,-305.41 -606.09,-292.61 DU1.K5@-612,-292.61 ; DU1.J5@-612,-267.02 v1(-624.79,-254.23) ; DU1.H5@-612,-241.43 v1(-624.79,-254.23) ; DU1.G5@-612,-215.84 -624.79,-228.64 v1(-624.79,-254.23) ; v1(-593.3,-254.23) DU1.J6@-580.5,-267.02 ; v1(-593.3,-254.23) DU1.H6@-580.5,-241.43 ; DU1.K6@-580.5,-292.61 v1(-567.71,-305.41) ; DC11.2@-561,96 v1(-530,96) ; DU1.U8@-517.51,-471.75 -517.51,-483.65 -514.5,-486.66 -514.5,-491.53 v1(-514.01,-492.02) ; DU1.N8@-517.51,-369.39 v1(-504.71,-382.18) ; DU1.K8@-517.51,-292.61 v1(-504.71,-305.41) ; DU1.H8@-517.51,-241.43 -506.92,-252.02 -502.02,-252.02 v1(-500.67,-253.38) ; DU1.E8@-517.51,-164.66 v1(-504.71,-151.87) ; DU1.A8@-517.51,-62.3 v1@-517.51,-47.48 ; v1@-517.51,-47.5 -517.51,-45.03 v1(-514.24,-41.76) ; DU1.U9@-486.01,-471.75 -486.01,-479.71 -485.51,-480.22 -485.51,-490.52 v1(-484.01,-492.02) ; DU1.A9@-486.01,-62.3 -486.01,-49.49 -483.55,-47.02 v1(-483.55,-43.56) ; v1(-424.24,-490.61) -424.24,-487.02 -423.02,-485.81 DU1.U11@-423.02,-471.75 ; DU1.H11@-423.02,-241.43 -428.93,-241.43 v1(-441.72,-254.23) DU1.J10@-454.52,-267.02 v1@-467.31,-254.23 ; DU1.R12@-391.53,-420.57 v1@-373.43,-420.57 ; DU1.N12@-391.53,-369.39 v1(-373.43,-369.39) ; DU1.H12@-391.53,-241.43 -386.19,-241.43 v1(-374.6,-253.02) ; v1(-89.56,-345.48) U1.P6@-76.77,-332.68 ; v1(-89.56,-319.89) U1.N6@-76.77,-307.09 ; v1(-89.56,-294.3) U1.M6@-76.77,-281.5 ; v1(-89.56,-268.7) U1.L6@-76.77,-255.91 ; v1(-89.56,-243.11) U1.K6@-76.77,-230.32 ; v1(-89.56,-217.52) U1.J6@-76.77,-204.73 ; v1@-467.31,-254.23 -480.11,-241.43 DU1.H9@-486.01,-241.43 -498.81,-254.23 DU1.J9@-486.01,-267.02 -480.11,-267.02 v1@-467.31,-254.23
  TOP w11.81: DC8.2@-756.99,42.14 -756.99,82.05 DR1.2@-755.89,83.14 -714.86,83.14 -707.27,90.73 DC12.2@-707.27,98.14 v1(-707.27,131.73) v1(-678.73,131.73) ; v1@-652.91,0.5 DC10.2@-637.27,16.14 ; v1@-87.56,-347.48 U1.R6@-76.77,-358.27 ; U1.F7@-51.18,-127.96 v1(-63.97,-115.17) U1.E7@-51.18,-102.37 ; v3(559.48,-689.81) U28.F15@572.27,-677.01 ; v3(636.25,-689.81) U28.F12@649.04,-677.01
  SIN04 w11.81: v3(559.48,-689.81) 580.67,-711 ; v2(601.73,-1012.36) 566.36,-1012.36 546,-992 546,-902.86 580.67,-868.19 580.67,-711 ; v3(636.25,-689.81) 615.05,-711 580.67,-711
  BOTTOM w10: DC17.2@-785.27,-466.86 v1(-785.27,-438.73) ; DC3.2@-751.27,-372.86 -747.82,-369.41 v1(-747.82,-343.8) -733.99,-329.96 DC15.2@-733.99,-319.86 ; v1(-89.56,-294.3) -62.85,-294.3 DC13.2@-62.08,-293.53 DC14.2@-62.08,-248.24 -67.21,-243.11 v1(-89.56,-243.11) ; v1@-62.08,-116.21 DC5.2@-62.08,-138.38 DC5.2@-60.76,-138.38
  BOTTOM w11.81: v1(-756,-31) DC4.2@-756,-5 ; v1(-654.41,2) -640.56,15.86 DC6.2@-637,15.86 ; C88.2@470.73,-640.24 494.49,-664 533.67,-664 v3(559.48,-689.81)
  other v1: -373.43,-419.57 -625.42,-406.9 -594.26,-406.81 -594.42,-305.41 -468.16,-254.23 -373.43,-167.16 -657.29,-128.28 -625.42,-127.9 -374.93,-110.48
  other v2: 601.73,-1037.86 634.73,-1037.86 633.73,-1012.36 601.73,-986.86
VCC-PD: C4.1 R328.1 R329.1 U1.F13 U1.F14 | length 309.7
  TOP w10: U1.F13@102.36,-127.96 v1(115.16,-115.16) U1.F14@127.95,-127.96 ; v1@203,43 211,51 R328.1@211,71 R329.1@248,71
  BOTTOM w10: v1(115.16,-115.16) 136.32,-94 C4.1@140,-94 163,-94 203,-54 v1(203,38)
VCC-RTC: C3.1 C19.2 C20.2 C70.2 C226.2 R33.1 R473.1 R474.1 U1.F8 U1.F12 U1.L14 U1.T8 U28.D8 U28.T14 | length 2607.6
  TOP w10: v1(-38.39,-396.65) U1.T8@-25.59,-383.86 ; v1(-38.39,-115.16) U1.F8@-25.59,-127.96 ; v1@63.98,-140.76 U1.F12@76.77,-127.96 ; U1.L14@127.95,-255.91 v1(140.75,-268.7)
  TOP w11.81: v3(585.07,-408.31) U28.T14@597.86,-421.1 ; v3(738.62,-740.98) U28.D8@751.41,-728.19
  SIN03 w10: v1(-38.39,-396.65) -73,-362.04 -73,-173 -38.39,-138.39 v1(-38.39,-115.16) -22.22,-99 22.31,-99 v1(63.31,-140)
  SIN03 w11.81: v1(140.75,-268.7) 140.75,-270.75 142.75,-270.75 209,-337 245,-337 274,-366 349,-366 v1@414,-431 ; v1(412,-824) 447,-824 455,-816 617,-816 684,-749 730.6,-749 v3(738.62,-740.98)
  SIN04 w10: v1(63.31,-140) 63.31,-191.27 v1(140.75,-268.7)
  SIN04 w11.81: v1(412,-824) 383,-795 383,-498 411.73,-469.27 v1(411.73,-430.86) 481.59,-361 578,-361 593,-376 593,-400.38 v3(585.07,-408.31) ; v3(738.62,-740.98) 758,-760.37 758,-827 742.73,-842.27 v2(742.73,-929.86)
  BOTTOM w10: C20.2@-64,-91 -62.55,-91 v1(-38.39,-115.16) ; C226.2@692.73,-734.86 698.85,-740.98 v3(738.62,-740.98)
  BOTTOM w11.81: v1(-38.39,-396.65) -38,-397.04 C3.1@-38,-420 ; v1(140.75,-268.7) 154,-255.45 C19.2@154,-242 ; C70.2@562.41,-342.24 590,-369.83 590,-403.38 v3(585.07,-408.31) ; R33.1@650.41,-902.24 723.08,-902.24 723.08,-910.21 v2(742.73,-929.86)
VCC_TP: C281.1 C282.1 J9.3 R129.2 | length 182.9
  TOP w10: 596.41,-75.17 J9.3@596.41,-40.86
  TOP w15: 500.73,-26.86 500.73,-67.86 518.73,-85.86 585.73,-85.86 596.41,-75.17
  other v1: 467.73,-12.86 489.73,-12.86 511.73,-12.86
VDD-CORE: C187.2 C188.2 U28.A9 | length 161.7
  TOP w11.81: U28.A9@725.82,-804.96 v3(738.62,-817.76)
  BOTTOM w12: v3(738.62,-817.76) 759.41,-838.55 ; C188.2@759.41,-868.41 759.41,-838.55 ; C187.2@834,-862.14 810.41,-838.55 759.41,-838.55
VDD-CPUA: C37.2 C38.2 C39.2 C41.2 C56.1 L2.2 U1.L9 U1.L10 U1.L11 U1.L12 U1.M9 U1.M11 U1.M12 U1.M13 U1.M14 | length 407
  TOP w10: U1.M14@127.95,-281.5 v1(115.16,-294.3) U1.M13@102.36,-281.5 ; v1(12.79,-268.7) U1.L9@0,-255.91 v1(-12.8,-268.7) U1.M9@0,-281.5 v1(12.79,-268.7) ; v1(12.79,-268.7) U1.L10@25.59,-255.91 38.39,-268.7 U1.L11@51.18,-255.91 v1(63.98,-268.7) ; v1(63.98,-268.7) U1.L12@76.77,-255.91 v1(89.57,-268.7) ; v1(63.98,-268.7) U1.M12@76.77,-281.5 ; v1(63.98,-268.7) U1.M11@51.18,-281.5 v1(63.98,-294.3) U1.M12@76.77,-281.5 ; U1.M12@76.77,-281.5 89.57,-294.3 U1.M13@102.36,-281.5 ; U1.M12@76.77,-281.5 v1(89.57,-268.7) ; v1(89.57,-268.7) U1.M13@102.36,-281.5
  BOTTOM w10: C38.2@39,-234 C38.2@48,-243 48,-252.73 v1(63.98,-268.7)
  other v2: 499.73,-245.86 521.73,-245.86 543.73,-245.86 500.73,-226.86 521.73,-226.86 542.73,-226.86
VDD-CPUB: C43.2 C44.2 C45.2 C46.2 C47.2 C59.1 L3.2 U1.F10 U1.F11 U1.H9 U1.H10 U1.H11 U1.J9 U1.J10 U1.J11 | length 524.9
  TOP w10: U1.J9@0,-204.73 v1(12.79,-191.93) U1.J10@25.59,-204.73 v1@38.39,-191.93 ; U1.H9@0,-179.14 v1(12.79,-191.93) U1.H10@25.59,-179.14 ; U1.H9@0,-179 12.8,-166.2 ; v1(12.79,-115.16) U1.F10@25.59,-127.96 v1(38.39,-140.76) ; U1.J11@51.18,-204.73 v1@38.39,-191.93 ; U1.F11@51.18,-127.96 v1(38.39,-140.76) ; 52,-155 63.66,-166.66 ; 63.98,-166.34 63.66,-166.66 ; 64.8,-167.8 63.66,-166.66 ; U1.H10@25.59,-179.14 38.39,-166.34 ; U1.H10@25.59,-179.14 v1(38.07,-191.62) v1@38.39,-191.93 ; U1.H10@25.59,-179.14 12.8,-166.34 25.59,-153.55 ; 25.59,-153.55 v1(38.39,-140.76) ; 25.59,-153.55 38.39,-166.34 ; v1@38.39,-191.93 U1.H11@51.18,-179.14 ; 38.39,-166.34 51.18,-153.55 v1(38.39,-140.76) ; 38.39,-166.34 U1.H11@51.18,-179.14 ; U1.H11@51.18,-179.14 63.66,-166.66
  BOTTOM w10: C47.2@-15,-194 10.73,-194 v1(12.79,-191.93) ; v1(12.79,-115.16) 12.79,-97.21 C46.2@18,-92 62,-92 C44.2@63,-91 ; C45.2@26,-163 38.39,-150.61 v1(38.39,-140.76)
  other v2: 655.73,-216.86 681.73,-216.86 708,-216.86 656.73,-196 681.73,-196 709,-196
VDD-GPU: C23.2 C24.2 C25.2 C26.2 C27.2 C63.1 L5.2 U1.P9 U1.P10 U1.P11 U1.T11 U28.N4 | length 631.1
  TOP w5.5: U28.N4@853.77,-497.87 892,-459.64 892,-415 883,-406 883,-394 841,-352 841,-264 L5.2@861,-244
  TOP w10: U1.P9@0,-332.68 v1(12.8,-345.48) ; v1(38.39,-319.89) U1.P10@25.59,-332.68 ; U1.P11@51.18,-332.68 v1(38.39,-345.48) ; v1(63.98,-396.65) U1.T11@51.18,-383.86 38.39,-371.07 ; v1(12.8,-345.48) U1.P10@25.59,-332.68 ; v1(12.8,-345.48) 25.59,-358.27 ; 25.59,-358.27 v1(38.39,-345.48) ; 25.59,-358.27 38.39,-371.07 ; U1.P10@25.59,-332.68 v1(38.39,-345.48) ; 38.39,-371.07 51.18,-358.27 ; v1(38.39,-345.48) 51.18,-358.27 ; v1(38.39,-345.48) 51.18,-358.27
  BOTTOM w10: C25.2@-12,-325.14 -7.54,-325.14 v1(12.8,-345.48) 12.79,-364.79 C24.2@19,-371 ; v1(38.39,-345.48) 61.91,-369 C27.2@64,-369
  other v2: 852.73,-216.86 876.73,-216.86 901,-216.86 852.73,-196 876.73,-196 899.73,-196
VDDFB-CPUA: U1.M10 U28.T11 | length 1411.4
  TOP w6: v1(12.79,-294.3) U1.M10@25.59,-281.5 ; v3(661.84,-408.31) U28.T11@674.63,-421.1
  SIN03 w6: v1(12.79,-294.3) -10,-317.09 -10,-346 -28,-364 -45,-364 -56,-353 -56,-181 -45.86,-170.86 57,-170.86 77.86,-150 100,-150 106,-156 123,-156 147,-132 147,-106 180.99,-72.01 202.01,-72.01 211,-81 366,-81 395,-110 454,-110 491,-73 550,-73 590,-113 590,-180 661.84,-251.84 v3(661.84,-408.31)
VDDFB-CPUB: U1.J12 U28.R11 | length 947.7
  TOP w6: U1.J12@76.77,-204.73 v1(89.57,-191.93) ; v3(661.84,-433.89) U28.R11@674.63,-446.69
  SIN03 w6: v1(89.57,-191.93) 113.5,-168 127,-168 159,-136 170,-136 210,-96 360,-96 388.16,-124.16 461.84,-124.16 496,-90 542,-90 571,-119 571,-181 638,-248 638,-410.05 v3(661.84,-433.89)
VDDIO: C4719.2 R5136.2 U4505.5 U4505.12 | length 359.3
  TOP w10: v2(232.73,-1359.86) C4719.2@271.28,-1359.86 271.28,-1343.41 262.04,-1334.17 U4505.5@262.04,-1304.05 ; U4505.12@301.41,-1203.66 v2(301.41,-1172.17)
  BOTTOM w10: v2(232.73,-1359.86) 255.73,-1359.86 268.35,-1347.24 R5136.2@268.35,-1298.86 268.35,-1279.65 286,-1262 286,-1231 301.41,-1215.59 v2(301.41,-1172.17)
VLED+: C132.2 C133.2 D12.2 OLED1.32 OLED1.33 TP41.1 U11.5 | length 1209
  SIN03 w10: v2@1256,-798.7 1318.7,-798.7 1332,-812 v1(1332,-936)
  SIN03 w15: v2(743.73,-1167.86) v2(743.73,-1187.86) 817.87,-1262 964,-1262 1093,-1133 1093,-1082 1113.47,-1061.53 1133.47,-1061.53 1145,-1050 1145,-1030 1166,-1009 1166,-954 1184,-936 v1(1332,-936)
  BOTTOM w10: v2@1254.73,-805.86 TP41.1@1269.73,-790.86 ; OLED1.32@1256.16,-947.13 1280.46,-947.13 1292.73,-934.86 ; 1357.73,-934.86 1358.18,-935.32
  BOTTOM w12: 1358.18,-935.32 OLED1.33@1385.29,-935.32
  BOTTOM w15: 1292.73,-934.86 1357.73,-934.86
  other v2: 1255.73,-798.7 1276,-799
VLED-: OLED1.34 OLED1.35 R85.2 R87.1 R1003.1 TP42.1 | length 362.6
  BOTTOM w10: R1003.1@1194.73,-889.63 R87.1@1194.73,-836.63 ; TP42.1@1194.73,-778.86 R87.1@1194.73,-836.63 ; R1003.1@1200.73,-889.63 R85.2@1200.73,-933.63 1210.85,-923.5 OLED1.34@1256.16,-923.5 1280.08,-923.5 1298.73,-904.86 1353.73,-904.86 1360.56,-911.69 OLED1.35@1385.29,-911.69 ; R87.1@1200.73,-842.63 R87.1@1194.73,-836.63
VOL+: ED27.1 J3.2 R132.1 | length 121.8
  TOP w10: J3.2@1176.25,-423.46 1178.52,-425.74 v2(1244.98,-425.74)
  BOTTOM w10: ED27.1@1215.11,-425.86 1245.11,-425.86 R132.1@1260.73,-441.48
VOL-: ED26.1 J3.1 R132.2 R133.1 | length 148.1
  TOP w10: J3.1@1176.25,-472.68 1180.43,-476.86 v2(1240.73,-476.86)
  BOTTOM w10: ED26.1@1215.73,-474.86 1217.73,-476.86 v2(1240.73,-476.86) R132.2@1260.73,-476.86 1262.73,-478.86 R133.1@1295.97,-478.86
WHITE: D39.2 R476.1 | length 563.8
  TOP w5: D39.2@-1302.86,-449.86 D39.2@-1304.34,-449.86 -1304.34,-425.34 -1295.86,-416.86 v1(-1263.27,-416.86) ; R476.1@-1064.92,-171.46 v1(-1025.67,-171.46)
  SIN03 w4: v1(-1263.27,-416.86) -1281,-399.13 -1281,-359 -1276,-354 -1168,-354 -1149.5,-335.5 -1094.5,-335.5 -1045,-286 -1045,-190.8 v1(-1025.67,-171.46)
WHITE_LED: R477.1 U1.V6 | length 1425.9
  TOP w4: v1(-89.57,-447.83) U1.V6@-76.77,-435.04
  TOP w5: R477.1@-1064.92,-207.86 v1(-1026.27,-207.86)
  SIN04 w4: v1(-1026.27,-207.86) -974.86,-207.86 -951,-184 -915,-184 -850,-249 -850,-496 -790,-556 -599.98,-556 -512.98,-643 -273,-643 -215,-585 -215,-573.26 v1(-89.57,-447.83)
WIFI-ANT: ANT1.1 C247.1 R318.1 | length 91.2
  TOP w5: ANT1.1@-1187.25,-1304.86 ccw(c-1184.84,-1302.44) ANT1.1@-1184.84,-1305.86
  TOP w15: ANT1.1@-1184.84,-1305.86 R318.1@-1096.27,-1305.86
WL-PMU-EN: R187.2 R191.1 U24.12 | length 107.4
  TOP w5: U24.12@-657.27,-1077.86 -657.27,-1078.86 -642.27,-1063.86 v2@-631.19,-1063.86
  BOTTOM w5: R187.2@-683.27,-1037.86 R191.1@-647.27,-1037.86 ; R191.1@-644.27,-1040.86 R191.1@-647.27,-1037.86 ; v2@-631.19,-1063.86 -631.19,-1051.94 -645.27,-1037.86 R191.1@-647.27,-1037.86
  other v2: -635.19,-1063.86
WL-SDIO-CLK: C315.2 R195.1 U1.K17 | length 2214.4
  TOP w4: U1.K17@204.72,-230.32 v1(217.52,-217.52)
  SIN04 w4: v2(-826.27,-978.86) -810.14,-978.86 -806,-983 -439,-983 -317.42,-1104.58 192.42,-1104.58 338,-959 338,-886 362,-862 362,-270 338,-246 245.99,-246 v1(217.52,-217.52)
  BOTTOM w5: R195.1@-853.27,-978.86 v2(-826.27,-978.86) -801.98,-978.86 C315.2@-799.72,-976.61
WL-SDIO-CMD: C314.2 R176.2 U1.K18 U24.16 | length 2412.2
  TOP w4: U1.K18@230.31,-230.32 v1(243.11,-217.52)
  TOP w5: v2(-826.27,-1016.86) -787.27,-1016.86 -706.53,-936.12 U24.16@-671.55,-936.12
  SIN04 w4: v2(-826.27,-1016.86) -802.41,-993 -442,-993 -320,-1115 196,-1115 370,-941 370,-265 340,-235 260.58,-235 v1(243.11,-217.52)
  BOTTOM w5: R176.2@-853.27,-1016.86 v2(-826.27,-1016.86) -802.23,-1016.86 C314.2@-799.72,-1014.36
WL-SDIO-D0: C316.2 R174.2 U1.L19 U24.18 | length 2293.3
  TOP w4: v1(243.1,-268.7) U1.L19@255.9,-255.91
  TOP w5: v2(-827.27,-940.86) -774.41,-888 -711,-888 -688.26,-865.26 U24.18@-671.55,-865.26
  SIN04 w4: v2(-827.27,-940.86) -805.14,-940.86 -783,-963 -431,-963 -310.25,-1083.75 185.25,-1083.75 317,-952 317,-879 341,-855 341,-304 305.71,-268.7 274,-268.7 ; v1(243.1,-268.7) 274,-268.7 ; 268.7,-268.7 274,-268.7
  BOTTOM w5: R174.2@-854.27,-940.86 R174.2@-853.27,-940.86 v2(-827.27,-940.86) -802.73,-940.86 C316.2@-800.72,-938.86
WL-SDIO-D1: C317.2 R173.2 U1.M16 U24.19 | length 2172.8
  TOP w4: U1.M16@179.13,-281.5 v1(191.93,-294.3)
  TOP w5: v2(-823,-848) -724,-848 -705.82,-829.82 U24.19@-671.55,-829.82
  SIN04 w4: v2(-823,-848) -706,-848 -664,-890 -439,-890 -297.33,-1031.67 113.33,-1031.67 232,-913 232,-822 285,-769 285,-589 261,-565 261,-418 271,-408 271,-382 236,-347 219.04,-347 191.93,-319.89 v1(191.93,-294.3)
  BOTTOM w5: R173.2@-854.27,-902.86 R173.2@-853.27,-902.86 -802.72,-902.86 C317.2@-801.72,-903.86 ; v2(-823,-848) -823,-862 -800.72,-884.28 C317.2@-800.72,-903.86
WL-SDIO-D2: C312.2 R178.2 U1.M17 U24.14 | length 2527.1
  TOP w4: U1.M17@204.72,-281.5 v1(217.52,-268.7)
  TOP w5: v2(-825.27,-1086.86) -782.41,-1044 -768,-1044 -730.99,-1006.99 U24.14@-671.55,-1006.99
  SIN04 w4: v2(-825.27,-1086.86) -804,-1065.59 -804,-1049 -818,-1035 -832,-1035 -851,-1016 -851,-976 -839,-964 -806,-964 -798,-972 -436,-972 -313.83,-1094.17 188.83,-1094.17 327,-956 327,-882 350,-859 350,-298 307,-255 231.22,-255 v1(217.52,-268.7)
  BOTTOM w5: R178.2@-853.27,-1092.86 -847.27,-1086.86 v2(-825.27,-1086.86) -802.72,-1086.86 C312.2@-799.72,-1089.86
WL-SDIO-D3: C313.2 R177.2 U1.M18 U24.15 | length 2434.7
  TOP w4: U1.M18@230.31,-281.5 v1(243.11,-294.3)
  TOP w5: v2(-826.27,-1054.86) -802.41,-1031 -775.41,-1031 -715.97,-971.56 U24.15@-671.55,-971.56
  SIN04 w4: v2(-826.27,-1054.86) -862,-1019.13 -862,-953 -832,-923 -803,-923 -772,-954 -428,-954 -308.67,-1073.33 180.67,-1073.33 306,-948 306,-875 329,-852 329,-567 306,-544 306,-427 317,-416 317,-297 300,-280 280,-280 265.7,-294.3 v1(243.11,-294.3)
  BOTTOM w5: R177.2@-853.27,-1054.86 v2(-826.27,-1054.86) -802.48,-1054.86 C313.2@-799.72,-1052.11
WL-WAKE-AP: U24.13
X24MI: C28.2 U1.U12 X1.1 | length 443.9
  TOP w4: U1.U12@76.77,-409.45 v1(89.57,-422.25)
  SIN04 w4: v1(89.57,-422.25) 123,-455.68 123,-481 154.33,-512.33 154.33,-578.67 v1(192,-616.33)
  BOTTOM w5: v1(192,-616.33) C28.2@210.53,-634.86 178,-667.39 178,-743 192.83,-757.83 X1.1@213.36,-757.83
X24MO: R5.2 U1.V13 | length 189.3
  TOP w4: v1(89.57,-447.84) U1.V13@102.36,-435.04
  BOTTOM w5: v1(89.57,-447.84) 140,-498.27 140,-549 127.62,-561.38 R5.2@127.62,-593
X32KI: C232.2 R169.2 U28.B9 X2.2 | length 614
  TOP w5: U28.B9@725.82,-779.37 v3(738.62,-792.17) ; C232.2@1052.66,-806.41 v2(1052.66,-787.86) 1052.66,-769.86 R169.2@1049.66,-766.86 1049.66,-713.36 X2.2@1058.37,-704.65
  SIN03 w4: v3(738.62,-792.17) 716,-814.78 716,-850 724,-858 744,-858 766,-836 813,-836 835,-858 955,-858 996.16,-816.84 996.16,-779.84 1004,-772 1036.81,-772 v2(1052.66,-787.86)
X32KO: C233.2 R169.1 U28.A10 X2.1 | length 558.3
  TOP w5: v3(687.44,-843.35) 687.44,-817.76 U28.A10@700.23,-804.96 ; X2.1@1007.19,-704.65 1007.19,-759.76 R169.1@1014.29,-766.86 1012.66,-768.48 v2(1012.66,-786.86) C233.2@1012.66,-806.41
  SIN03 w4: v3(687.44,-843.35) 712.09,-868 748.14,-868 770.14,-846 808.86,-846 830.86,-868 969,-868 1012.66,-824.34 v2(1012.66,-786.86)
XTAL-IN: R184.2 U24.10 | length 188.4
  TOP w5: U24.10@-757.18,-1128.05 -757.18,-1091.77 v2(-739.27,-1073.86)
  BOTTOM w5: v2(-739.27,-1073.86) -720.27,-1073.86 -707.27,-1086.86 -658.14,-1086.86 -620.65,-1086.86 R184.2@-618.65,-1088.86
XTAL-OUT: R185.1 U24.11 | length 116.7
  TOP w5: U24.11@-721.75,-1128.05 U24.11@-718.27,-1124.57
  BOTTOM w5: v2(-719.27,-1098.86) -645.65,-1098.86 R185.1@-618.65,-1125.86
pads on no net: DU1.A1 DU1.A2 DU1.A12 DU1.A13 DU1.B1 DU1.B13 DU1.C4 DU1.K9 DU1.R3 DU1.T1 DU1.T13 DU1.U1 DU1.U2 DU1.U12 DU1.U13 J8. J8.11 J8.12 J8.13 J4700.24 J4700.28 J4702.5 J4702.7 OLED1.6 OLED1.9 OLED1.13 OLED1.17 OLED1.21 OLED1.25 OLED1.38 OLED1.39 OU1.6 SHIELD12_1.1@383.73,36 SHIELD12_1.1@383.73,-819 SHIELD12_1.1@716,-1369.86 SHIELD12_1.1@723,-146.86 SHIELD12_1.1@1087.73,-349 SHIELD12_1.1@1087.73,-1145 SHIELD12_1.1@-110,-1099.86 SHIELD12_1.1@-494,198.14 SHIELD12_1.1@-566.27,-781 SHIELD12_1.1@-607.27,-898 SHIELD12_1.1@-847.27,-158 SHIELD12_1.1@-902,-597.86 SHIELD12_1.2@200.06,198.14 SHIELD12_1.2@383.73,95.06 SHIELD12_1.2@383.73,-759.94 SHIELD12_1.2@663.94,-146.86 SHIELD12_1.2@775.06,-1369.86 SHIELD12_1.2@1087.73,-408.06 SHIELD12_1.2@1087.73,-1204.06 SHIELD12_1.2@-50.94,-1099.86 SHIELD12_1.2@-434.94,198.14 SHIELD12_1.2@-566.27,-721.94 SHIELD12_1.2@-607.27,-957.06 SHIELD12_1.2@-842.94,-597.86 SHIELD12_1.2@-847.27,-98.94 SHIELD12_1.3@8.11,-1099.86 SHIELD12_1.3@259.11,198.14 SHIELD12_1.3@383.73,154.11 SHIELD12_1.3@604.89,-146.86 SHIELD12_1.3@834.11,-1369.86 SHIELD12_1.3@1087.73,-467.11 SHIELD12_1.3@1087.73,-1263.11 SHIELD12_1.3@-375.89,198.14 SHIELD12_1.3@-566.27,-662.89 SHIELD12_1.3@-607.27,-1016.11 SHIELD12_1.3@-783.89,-597.86 SHIELD12_1.3@-847.27,-39.89 SHIELD12_1.4@81.94,198.14 SHIELD12_1.4@383.73,-23.06 SHIELD12_1.4@383.73,-878.06 SHIELD12_1.4@656.94,-1369.86 SHIELD12_1.4@782.06,-146.86 SHIELD12_1.4@1087.73,-289.94 SHIELD12_1.4@1087.73,-1085.94 SHIELD12_1.4@-169.06,-1099.86 SHIELD12_1.4@-553.06,198.14 SHIELD12_1.4@-566.27,-840.06 SHIELD12_1.4@-607.27,-838.94 SHIELD12_1.4@-847.27,-217.06 SHIELD12_1.4@-961.06,-597.86 SHIELD12_1.5@22.89,198.14 SHIELD12_1.5@383.73,-82.11 SHIELD12_1.5@383.73,-937.11 SHIELD12_1.5@597.89,-1369.86 SHIELD12_1.5@841.11,-146.86 SHIELD12_1.5@1087.73,-230.89 SHIELD12_1.5@1087.73,-1026.89 SHIELD12_1.5@-228.11,-1099.86 SHIELD12_1.5@-566.27,-899.11 SHIELD12_1.5@-607.27,-779.89 SHIELD12_1.5@-612.11,198.14 SHIELD12_1.5@-847.27,-276.11 SHIELD12_1.5@-1020.11,-597.86 SW8.5 SW8.6 SW9.5 SW9.6 U1.AA6 U1.B10 U1.B11 U1.C5 U1.D4 U1.D6 U1.D7 U1.D10 U1.E6 U1.E10 U1.F1 U1.F2 U1.F4 U1.G1 U1.G2 U1.G5 U1.J18 U1.J20 U1.J21 U1.K19 U1.K20 U1.K21 U1.L20 U1.M20 U1.M21 U1.P3 U1.R4 U1.R5 U1.R18 U1.T4 U1.U3 U1.U7 U1.V4 U1.V15 U1.V16 U1.V20 U1.V21 U1.W5 U1.W16 U1.Y7 U1.Y14 U1.Y19 U1.Y21 U24.4 U24.5 U24.8 U24.32 U24.35 U24.37 U24.38 U24.39 U24.40 U24.45 U24.46 U24.47 U28.A1 U28.A2 U28.A3 U28.A6 U28.A7 U28.A8 U28.B1 U28.B2 U28.B3 U28.B6 U28.B7 U28.B8 U28.C8 U28.D15 U28.G16 U28.H15 U28.M1 U28.R4 U28.R13 U28.R14 U28.T3 U28.T13 U29.A4 U29.A6 U29.A9 U29.A11 U29.AA1 U29.AA2 U29.AA7 U29.AA8 U29.AA9 U29.AA10 U29.AA11 U29.AA12 U29.AA13 U29.AA14 U29.AE1 U29.AE14 U29.AG2 U29.AG13 U29.AH4 U29.AH6 U29.AH9 U29.AH11 U29.B2 U29.B13 U29.D1 U29.D14 U29.H1 U29.H8 U29.H9 U29.H10 U29.H11 U29.H12 U29.H13 U29.H14 U29.J1 U29.J7 U29.J8 U29.J9 U29.J10 U29.J11 U29.J12 U29.J13 U29.J14 U29.K3 U29.K7 U29.K8 U29.K9 U29.K10 U29.K11 U29.K12 U29.K13 U29.K14 U29.L1 U29.L2 U29.L3 U29.L12 U29.L13 U29.L14 U29.M1 U29.M2 U29.M3 U29.M5 U29.M8 U29.M9 U29.M10 U29.M12 U29.M13 U29.M14 U29.N1 U29.N2 U29.N3 U29.N10 U29.N12 U29.N13 U29.N14 U29.P1 U29.P2 U29.P3 U29.P10 U29.P12 U29.P13 U29.P14 U29.R1 U29.R2 U29.R3 U29.R5 U29.R12 U29.R13 U29.R14 U29.T1 U29.T2 U29.T3 U29.T12 U29.T13 U29.T14 U29.U1 U29.U2 U29.U3 U29.U6 U29.U7 U29.U10 U29.U12 U29.U13 U29.U14 U29.V1 U29.V2 U29.V3 U29.V12 U29.V13 U29.V14 U29.W1 U29.W2 U29.W3 U29.W7 U29.W8 U29.W9 U29.W10 U29.W11 U29.W12 U29.W13 U29.W14 U29.Y3 U29.Y6 U29.Y7 U29.Y8 U29.Y9 U29.Y10 U29.Y11 U29.Y12 U29.Y13 U29.Y14 U30.1 U30.2 U30.3 U30.4 U30.5 U30.6 U30.14 U30.15 U30.16 U30.17 U30.19 U30.25 U101.1 U101.5 U1000.5 U4505.10 U4505.11 X2.0
copper on no net:
  other v1: -429,-1296 204,-1188 -394,-1134 515,-1066 -716,-1036 146,-1026 246,-901 157,-877 -1381,-861 -513,-841 -447.6,-839 -312,-839 -927,-838 154,-821 -1384,-787 32,-763 -994,-739 158,-707 -1381,-690 1332,-436 1337,-354 -900,-173 12.79,-140.76 -1368,-133 -1281,-131 -1176,-131 -1064.08,-127.45 -1174,-5 673,30 -1377,37 674,51 -10,71 27,92 -603,135 -518,136 -471,152 -67,164 1292.73,345.58 -587,349 -282,369 -452,370 -373,370 -865,387 1339,453 326,498 387,498 273,500 1002,501 1157,504
  other v2: 417.73,-1286.86 443.73,-1286.86 442.73,-1254.86 1349.73,-714.86 1271.73,-404.86 1267.73,-366.86 1269.73,-329.86 1333.18,-296.31 417.73,-250.86 443.73,-249.86 1039.73,-216.86 1038.73,-196
  other v3: 815.39,-817.75 815.39,-792.16 585.07,-433.9

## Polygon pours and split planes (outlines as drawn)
GND on BOTTOM "TopLayer-No Net" (hatched 90Degree grid 4 track 5, remove dead copper, pour order 1004): 542,-893 622,-893 622,-915 622,-932 691,-932 726,-932 726,-958 726,-965 652,-965 542,-965 542,-893
GND on BOTTOM "TopLayer-No Net" (hatched 90Degree grid 4 track 5, remove dead copper, pour order 1003): 806,-1012 848,-1012 848,-1049 848,-1094 789,-1094 780,-1094 780,-1072 780,-1060 807,-1060 806,-1060 806,-1012
USB-5V on BOTTOM "TopLayer-No Net" (hatched 90Degree grid 4 track 5, remove dead copper, pour order 1002): 135,348 230,348 230,332 194,296 185,296 135,296 135,348
USBVBUS on BOTTOM "TopLayer-No Net" (hatched Horizontal grid 4 track 5, remove dead copper, pour order 1001): 31 vertices, not listed, extent 220,-412 481,412
DCIN on BOTTOM "Top Layer-No Net" (hatched 90Degree grid 4 track 5, remove dead copper, pour order 1000): 457,-275 457,-333 406,-333 406,-275
DCDC6 on BOTTOM "Top Layer-No Net" (hatched 90Degree grid 4 track 5, remove dead copper, pour order 1000): 736,-1040.86 736,-958.86 786.73,-958.86 786.73,-1040.86
DCDC6 on BOTTOM "TopLayer-No Net" (hatched 90Degree grid 4 track 5, remove dead copper, pour order 1000): 156,-163 220,-163 220,-171 220,-249 200,-249 176,-249 176,-234 176,-231 154,-231 105,-231 105,-202 105,-183 132,-183 156,-183 156,-163
PS on BOTTOM "Top Layer-No Net" (hatched 90Degree grid 4 track 5, remove dead copper, pour order 1009): 1252.73,-97.86 1252.73,-226 1325.73,-226 1325.73,-174.86 1303.73,-174.86 1303.73,-97.86
LCD_+V50AP on BOTTOM "Top Layer-No Net" (hatched 90Degree grid 4 track 5, remove dead copper, pour order 1005): 1190,-1003 1212,-1003 1212,-1013 1212,-1056 1185,-1056 1159,-1056 1159,-1040 1159,-1035 1175,-1035 1190,-1035 1190,-1003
